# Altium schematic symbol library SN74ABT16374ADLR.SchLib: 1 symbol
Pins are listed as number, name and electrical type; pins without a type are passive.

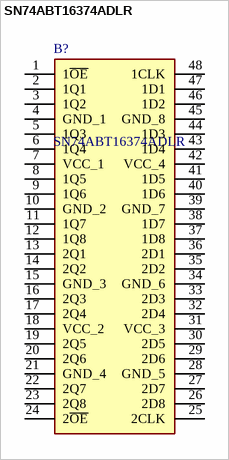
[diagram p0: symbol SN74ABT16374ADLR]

## SN74ABT16374ADLR
designator B?
16-Bit Edge-Triggered D-Type Fflip-Flops With 3-State Outputs; Manufacturer_Name: Texas Instruments; Geometry.Height: 2.79mm
footprint SOP64P1035X279-48N
pins: 1 1~{OE}, 2 1Q1, 3 1Q2, 4 GND_1, 5 1Q3, 6 1Q4, 7 VCC_1, 8 1Q5, 9 1Q6, 10 GND_2, 11 1Q7, 12 1Q8, 13 2Q1, 14 2Q2, 15 GND_3, 16 2Q3, 17 2Q4, 18 VCC_2, 19 2Q5, 20 2Q6, 21 GND_4, 22 2Q7, 23 2Q8, 24 2~{OE}, 25 2CLK, 26 2D8, 27 2D7, 28 GND_5, 29 2D6, 30 2D5, 31 VCC_3, 32 2D4, 33 2D3, 34 GND_6, 35 2D2, 36 2D1, 37 1D8, 38 1D7, 39 GND_7, 40 1D6, 41 1D5, 42 VCC_4, 43 1D4, 44 1D3, 45 GND_8, 46 1D2, 47 1D1, 48 1CLK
